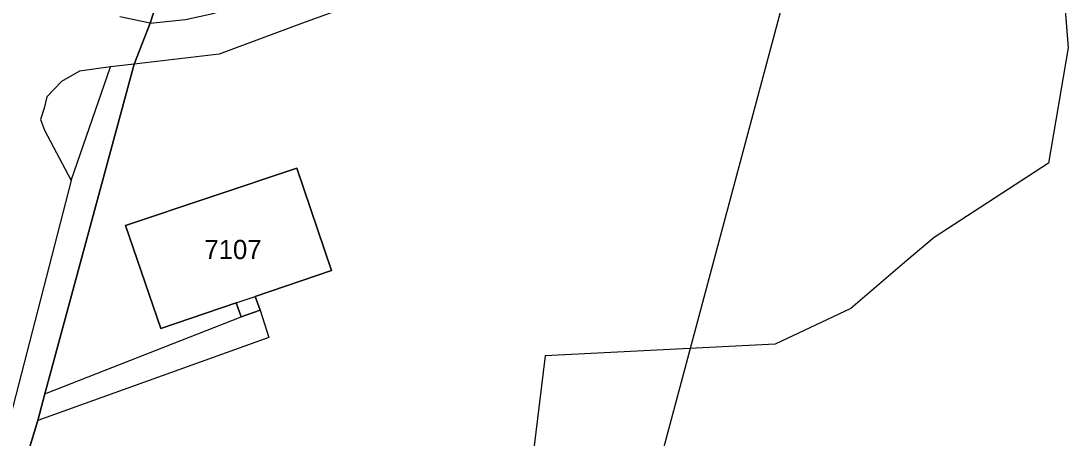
# Model space of a CAD drawing. Extents: x -266199 to -261993, y -1239047 to -1235108.
# Drawn here: x -263495.6 to -263386.5, y -1236393.3 to -1236349.9 of the extents above; entities that cross this region are included whole.
import ezdxf

# ---------------------------------------------------------------- set-up
doc = ezdxf.new("R2010")
doc.units = 0
for name, color, linetype in [('body_kn', 7, 'Continuous'), ('kladpar_druhypozemkov', 7, 'Continuous'), ('kladpar_hranice', 7, 'Continuous'), ('kladpar_parcelnecisla', 7, 'Continuous'), ('kladpar_plochy', 7, 'Continuous'), ('zappar_hrandruhpozemk', 7, 'Continuous'), ('zuob_linie', 7, 'Continuous'), ('zuob_plochy', 7, 'Continuous')]:
    doc.layers.add(name, color=color, linetype=linetype)

msp = doc.modelspace()

# ---------------------------------------------------------------- linework, layer by layer
at = {"layer": 'body_kn'}
for p, q in [((-263482.16, -1236350.08), (-263482.16, -1236350.08)), ((-263482.16, -1236350.08), (-263482.16, -1236350.08)), ((-263466.28, -1236350.1), (-263466.28, -1236350.1)), ((-263386.53, -1236352.65), (-263386.53, -1236352.65)), ((-263474.98, -1236353.32), (-263474.98, -1236353.32)), ((-263486.29, -1236354.65), (-263486.29, -1236354.65)), ((-263486.29, -1236354.65), (-263486.29, -1236354.65)), ((-263483.85, -1236354.35), (-263483.85, -1236354.35)), ((-263483.85, -1236354.35), (-263483.85, -1236354.35)), ((-263489.53, -1236355.11), (-263489.53, -1236355.11)), ((-263491.4, -1236356.17), (-263491.4, -1236356.17)), ((-263492.93, -1236357.78), (-263492.93, -1236357.78)), ((-263493.2, -1236358.96), (-263493.2, -1236358.96)), ((-263493.58, -1236360.12), (-263493.58, -1236360.12)), ((-263493.17, -1236361.25), (-263493.17, -1236361.25)), ((-263388.58, -1236364.67), (-263388.58, -1236364.67)), ((-263466.89, -1236365.18), (-263466.89, -1236365.18)), ((-263490.4, -1236366.47), (-263490.4, -1236366.47)), ((-263490.4, -1236366.47), (-263490.4, -1236366.47)), ((-263484.72, -1236371.17), (-263484.72, -1236371.17)), ((-263400.47, -1236372.4), (-263400.47, -1236372.4)), ((-263403.32, -1236374.82), (-263403.32, -1236374.82)), ((-263463.26, -1236375.85), (-263463.26, -1236375.85)), ((-263471.22, -1236378.54), (-263471.22, -1236378.54)), ((-263473.19, -1236379.21), (-263473.19, -1236379.21)), ((-263473.19, -1236379.21), (-263473.19, -1236379.21)), ((-263470.69, -1236379.99), (-263470.69, -1236379.99)), ((-263470.69, -1236379.99), (-263470.69, -1236379.99)), ((-263409.18, -1236379.8), (-263409.18, -1236379.8)), ((-263472.69, -1236380.66), (-263472.69, -1236380.66)), ((-263481.07, -1236381.88), (-263481.07, -1236381.88)), ((-263481.07, -1236381.88), (-263481.07, -1236381.88)), ((-263469.8, -1236382.82), (-263469.8, -1236382.82)), ((-263417.03, -1236383.53), (-263417.03, -1236383.53)), ((-263441.01, -1236384.73), (-263441.01, -1236384.73)), ((-263493.13, -1236388.68), (-263493.13, -1236388.68)), ((-263493.13, -1236388.68), (-263493.13, -1236388.68)), ((-263493.88, -1236391.47), (-263493.88, -1236391.47))]:
    msp.add_line(p, q, dxfattribs=at)
at = {"layer": 'kladpar_druhypozemkov'}
for p, q in [((-263473.58, -1236372.06), (-263473.58, -1236372.06)), ((-263482.57, -1236386.9), (-263482.57, -1236386.9))]:
    msp.add_line(p, q, dxfattribs=at)
at = {"layer": 'kladpar_hranice'}
msp.add_line((-263396.48, -1236274.15), (-263473.03, -1236559.71), dxfattribs=at)
for points in [[(-263443.64, -1236260.69), (-263441.39, -1236276.72), (-263454.42, -1236281.13), (-263456.32, -1236276.84), (-263462.86, -1236294.64), (-263472.22, -1236319.89), (-263473.61, -1236323.66), (-263482.16, -1236350.08), (-263483.85, -1236354.35), (-263493.13, -1236388.68), (-263493.88, -1236391.47), (-263497.9, -1236404.63), (-263499.74, -1236413.8), (-263500.72, -1236421.9), (-263501.51, -1236432.4), (-263501.66, -1236434.96), (-263502.07, -1236444.61)], [(-263497.9, -1236404.63), (-263493.88, -1236391.47), (-263493.13, -1236388.68), (-263483.85, -1236354.35), (-263482.16, -1236350.08), (-263473.61, -1236323.66), (-263472.22, -1236319.89), (-263462.86, -1236294.64), (-263456.32, -1236276.84), (-263454.42, -1236281.13), (-263441.39, -1236276.72), (-263443.64, -1236260.69)], [(-263396.48, -1236274.15), (-263395.17, -1236279.46), (-263390.68, -1236297.73), (-263390.41, -1236303.51), (-263389.8, -1236311.14), (-263388.68, -1236325.22), (-263387.51, -1236339.82), (-263386.53, -1236352.65), (-263388.58, -1236364.67), (-263400.47, -1236372.4), (-263403.32, -1236374.82), (-263409.18, -1236379.8), (-263417.03, -1236383.53), (-263441.01, -1236384.73), (-263442.2, -1236394.4)], [(-263481.07, -1236381.88), (-263484.72, -1236371.17), (-263466.89, -1236365.18), (-263463.26, -1236375.85), (-263471.22, -1236378.54), (-263470.69, -1236379.99), (-263472.69, -1236380.66), (-263473.19, -1236379.21), (-263481.07, -1236381.88)], [(-263484.72, -1236371.17), (-263481.07, -1236381.88), (-263473.19, -1236379.21), (-263472.69, -1236380.66), (-263470.69, -1236379.99), (-263471.22, -1236378.54), (-263463.26, -1236375.85), (-263466.89, -1236365.18), (-263484.72, -1236371.17)]]:
    msp.add_lwpolyline(points, dxfattribs=at)
at = {"layer": 'kladpar_plochy'}
for p, q in [((-263482.16, -1236350.08), (-263473.61, -1236323.66)), ((-263387.51, -1236339.82), (-263386.53, -1236352.65)), ((-263483.85, -1236354.35), (-263482.16, -1236350.08)), ((-263386.53, -1236352.65), (-263388.58, -1236364.67)), ((-263493.13, -1236388.68), (-263483.85, -1236354.35)), ((-263388.58, -1236364.67), (-263400.47, -1236372.4)), ((-263466.89, -1236365.18), (-263484.72, -1236371.17)), ((-263463.26, -1236375.85), (-263466.89, -1236365.18)), ((-263484.72, -1236371.17), (-263481.07, -1236381.88)), ((-263400.47, -1236372.4), (-263403.32, -1236374.82)), ((-263403.32, -1236374.82), (-263409.18, -1236379.8)), ((-263471.22, -1236378.54), (-263463.26, -1236375.85)), ((-263470.69, -1236379.99), (-263471.22, -1236378.54)), ((-263481.07, -1236381.88), (-263473.19, -1236379.21)), ((-263473.19, -1236379.21), (-263472.69, -1236380.66)), ((-263472.69, -1236380.66), (-263470.69, -1236379.99)), ((-263409.18, -1236379.8), (-263417.03, -1236383.53)), ((-263417.03, -1236383.53), (-263441.01, -1236384.73)), ((-263441.01, -1236384.73), (-263442.2, -1236394.4)), ((-263493.88, -1236391.47), (-263493.13, -1236388.68)), ((-263497.9, -1236404.63), (-263493.88, -1236391.47))]:
    msp.add_line(p, q, dxfattribs=at)
msp.add_lwpolyline([(-263443.64, -1236260.69), (-263441.39, -1236276.72), (-263454.42, -1236281.13), (-263456.32, -1236276.84), (-263462.86, -1236294.64), (-263472.22, -1236319.89), (-263473.61, -1236323.66), (-263482.16, -1236350.08), (-263483.85, -1236354.35), (-263493.13, -1236388.68), (-263493.88, -1236391.47), (-263497.9, -1236404.63), (-263499.74, -1236413.8), (-263500.72, -1236421.9), (-263501.51, -1236432.4), (-263501.66, -1236434.96), (-263502.07, -1236444.61), (-263500.5, -1236448.76), (-263501.28, -1236460.62), (-263502.42, -1236480.32)], dxfattribs=at)
msp.add_lwpolyline([(-263481.07, -1236381.88), (-263484.72, -1236371.17), (-263466.89, -1236365.18), (-263463.26, -1236375.85), (-263471.22, -1236378.54), (-263470.69, -1236379.99), (-263472.69, -1236380.66), (-263473.19, -1236379.21)], close=True, dxfattribs=at)
at = {"layer": 'zappar_hrandruhpozemk'}
for p, q in [((-263445.43, -1236342.49), (-263466.28, -1236350.1)), ((-263482.16, -1236350.08), (-263485.31, -1236349.42)), ((-263490.4, -1236366.47), (-263486.29, -1236354.65)), ((-263483.85, -1236354.35), (-263486.29, -1236354.65)), ((-263490.4, -1236366.47), (-263497.02, -1236392.19)), ((-263473.19, -1236379.21), (-263471.22, -1236378.54)), ((-263470.69, -1236379.99), (-263469.8, -1236382.82)), ((-263493.13, -1236388.68), (-263472.69, -1236380.66)), ((-263469.8, -1236382.82), (-263493.88, -1236391.47))]:
    msp.add_line(p, q, dxfattribs=at)
for points in [[(-263482.16, -1236350.08), (-263478.49, -1236349.73), (-263475.64, -1236349.08), (-263470.77, -1236347.51), (-263464.97, -1236345.38), (-263463.98, -1236344.05)], [(-263466.28, -1236350.1), (-263474.98, -1236353.32), (-263483.85, -1236354.35)], [(-263486.29, -1236354.65), (-263489.53, -1236355.11), (-263491.4, -1236356.17), (-263492.93, -1236357.78), (-263493.2, -1236358.96), (-263493.58, -1236360.12), (-263493.17, -1236361.25), (-263490.4, -1236366.47)]]:
    msp.add_lwpolyline(points, dxfattribs=at)
at = {"layer": 'zuob_linie'}
msp.add_lwpolyline([(-263397.93, -1236262.41), (-263393.42, -1236263.62), (-263389.22, -1236276.07), (-263389.33, -1236280.76), (-263389.6, -1236291.71), (-263390.68, -1236297.73), (-263390.41, -1236303.51), (-263389.8, -1236311.14), (-263388.68, -1236325.22), (-263387.51, -1236339.82), (-263386.53, -1236352.65), (-263388.58, -1236364.67), (-263400.47, -1236372.4), (-263403.32, -1236374.82), (-263409.18, -1236379.8), (-263417.03, -1236383.53), (-263441.01, -1236384.73), (-263442.2, -1236394.4)], dxfattribs=at)
at = {"layer": 'zuob_plochy'}
msp.add_lwpolyline([(-263397.93, -1236262.41), (-263393.42, -1236263.62), (-263389.22, -1236276.07), (-263389.33, -1236280.76), (-263389.6, -1236291.71), (-263390.68, -1236297.73), (-263390.41, -1236303.51), (-263389.8, -1236311.14), (-263388.68, -1236325.22), (-263387.51, -1236339.82), (-263386.53, -1236352.65), (-263388.58, -1236364.67), (-263400.47, -1236372.4), (-263403.32, -1236374.82), (-263409.18, -1236379.8), (-263417.03, -1236383.53), (-263441.01, -1236384.73), (-263442.2, -1236394.4)], dxfattribs=at)

# ---------------------------------------------------------------- texts
at = {"layer": 'kladpar_parcelnecisla'}
msp.add_text('7107', height=2, dxfattribs=at).set_placement((-263476.51, -1236374.66))

doc.saveas('drawing.dxf')
